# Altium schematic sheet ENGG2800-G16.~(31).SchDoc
size A3
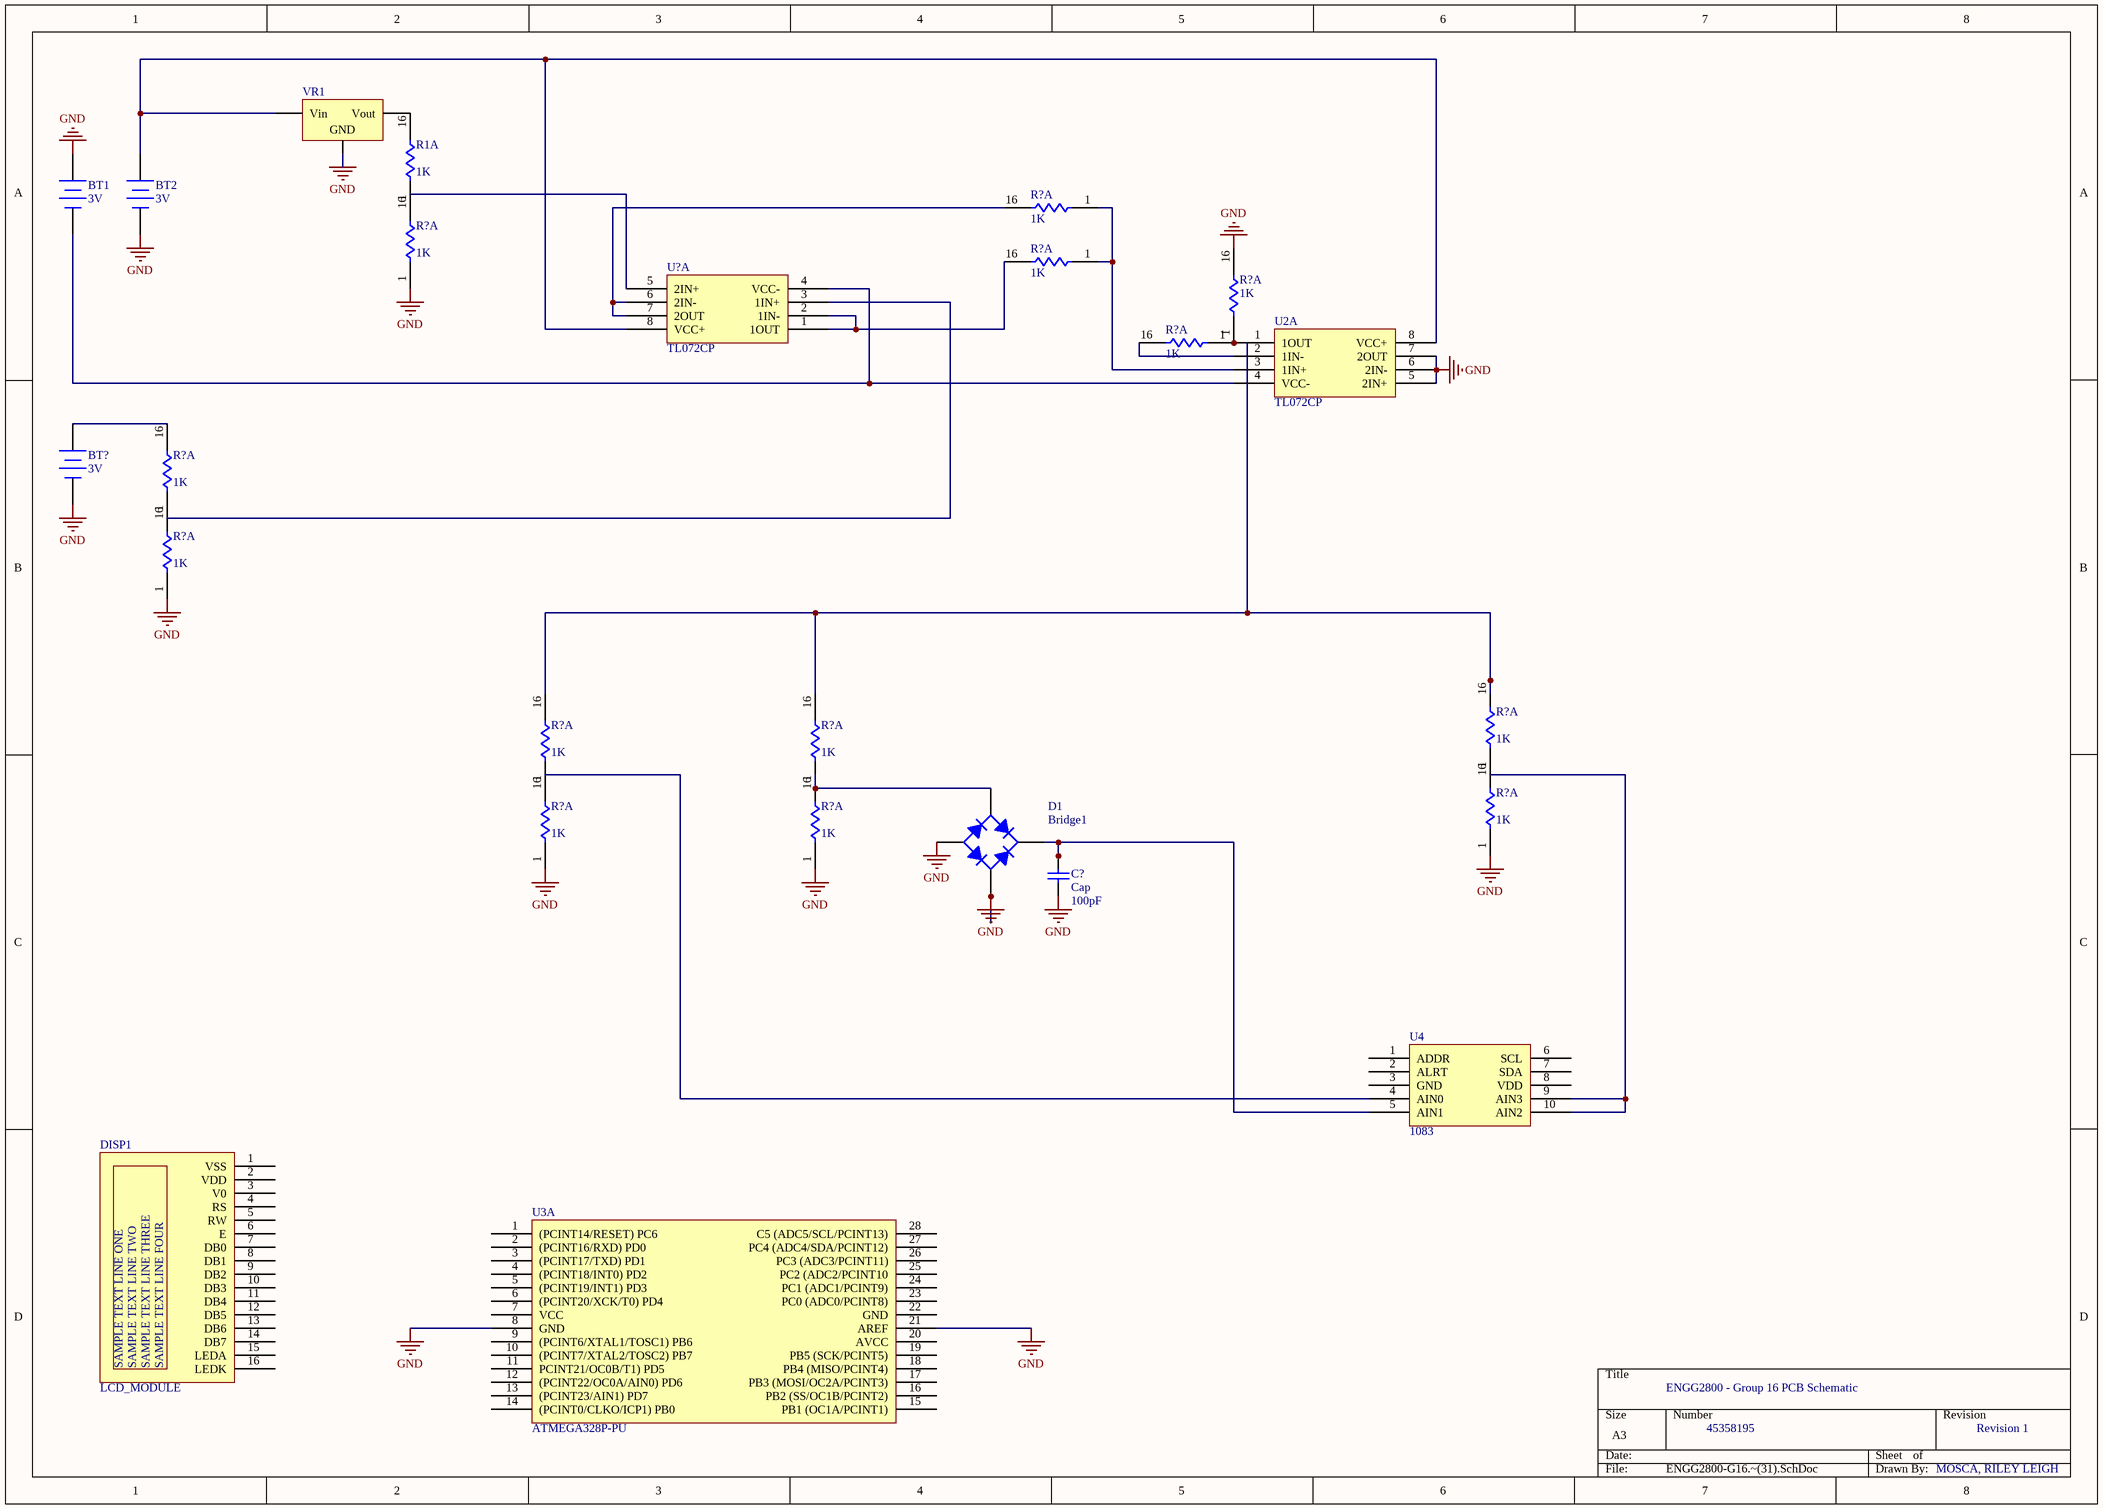
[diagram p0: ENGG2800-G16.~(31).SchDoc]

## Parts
(Parts that share a designator on the sheet are numbered #1, #2 ... from top to bottom, then left to right.)
BT1  3V  [BAT-2]
BT2  3V  [BAT-2]
BT?  3V  [BAT-2]
C?  Cap  value 100pF  [RAD-0.3]
D1  Bridge1  [D-38]
DISP1  LCD_MODULE
R1  value 1K  [SOIC16_N]  (hidden comment: Res Pack1)  (part A of 8)
R?#1  value 1K  [SOIC16_N]  (hidden comment: Res Pack1)  (part A of 8)
R?#2  value 1K  [SOIC16_N]  (hidden comment: Res Pack1)  (part A of 8)
R?#3  value 1K  [SOIC16_N]  (hidden comment: Res Pack1)  (part A of 8)
R?#4  value 1K  [SOIC16_N]  (hidden comment: Res Pack1)  (part A of 8)
R?#5  value 1K  [SOIC16_N]  (hidden comment: Res Pack1)  (part A of 8)
R?#6  value 1K  [SOIC16_N]  (hidden comment: Res Pack1)  (part A of 8)
R?#7  value 1K  [SOIC16_N]  (hidden comment: Res Pack1)  (part A of 8)
R?#8  value 1K  [SOIC16_N]  (hidden comment: Res Pack1)  (part A of 8)
R?#9  value 1K  [SOIC16_N]  (hidden comment: Res Pack1)  (part A of 8)
R?#10  value 1K  [SOIC16_N]  (hidden comment: Res Pack1)  (part A of 8)
R?#11  value 1K  [SOIC16_N]  (hidden comment: Res Pack1)  (part A of 8)
R?#12  value 1K  [SOIC16_N]  (hidden comment: Res Pack1)  (part A of 8)
R?#13  value 1K  [SOIC16_N]  (hidden comment: Res Pack1)  (part A of 8)
U2  TL072CP  (part A of 4)
U3  ATMEGA328P-PU  (part A of 2)
U4  1083
U?  TL072CP  (part A of 4)
VR1  Volt Reg  [D2PAK_N]  (value not drawn)

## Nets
GND: BT1.1(+) BT2.2(-) BT?.2(-) C?.1 D1.2(C) D1.3(A) R?#2.1 R?#4.16 R?#7.1 R?#11.1 R?#12.1 R?#13.1 U2.5(2IN+) U2.6(2IN-) U2.7(2OUT) U3.8(GND) U3.21(AREF) VR1.2(GND)
NetBT1_2: BT1.2(-) U2.4(VCC-) U?.4(VCC-)
NetBT2_1: BT2.1(+) U2.8(VCC+) U?.8(VCC+) VR1.1(Vin)
NetBT?_1: BT?.1(+) R?#6.16
NetC?_2: C?.2 D1.1(K) U4.5(AIN1)
NetD1_4: D1.4(C) R?#10.1 R?#13.16
NetR1_16: R1.16 VR1.3(Vout)
NetR?#1_1: R?#1.1 R?#3.1 U2.3(1IN+)
NetR?#1_16: R?#1.16 U?.6(2IN-) U?.7(2OUT)
NetR?#2_16: R?#2.16 U?.5(2IN+)
NetR?#3_16: R?#3.16 U?.1(1OUT) U?.2(1IN-)
NetR?#4_1: R?#4.1 R?#5.1 U2.1(1OUT)
NetR?#5_16: R?#5.16 U2.2(1IN-)
NetR?#6_1: R?#6.1 U?.3(1IN+)
NetR?#8_1: R?#8.1 U4.9(AIN3) U4.10(AIN2)
NetR?#8_16: R?#8.16 R?#9.16 R?#10.16
NetR?#12_16: R?#12.16 U4.4(AIN0)

Not connected (* = marked no-connect by the designer): DISP1 1(VSS) 2(VDD) 3(V0) 4(RS) 5(RW) 6(E) 7(DB0) 8(DB1) 9(DB2) 10(DB3) 11(DB4) 12(DB5) 13(DB6) 14(DB7) 15(LEDA) 16(LEDK); R1 1; R?#7 16; R?#9 1; R?#11 16; U3 1((PCINT14/RESET)_PC6) 2((PCINT16/RXD)_PD0) 3((PCINT17/TXD)_PD1) 4((PCINT18/INT0)_PD2) 5((PCINT19/INT1)_PD3) 6((PCINT20/XCK/T0)_PD4) 7(VCC) 9((PCINT6/XTAL1/TOSC1)_PB6) 10((PCINT7/XTAL2/TOSC2)_PB7) 11(PCINT21/OC0B/T1)_PD5) 12((PCINT22/OC0A/AIN0)_PD6) 13((PCINT23/AIN1)_PD7) 14((PCINT0/CLKO/ICP1)_PB0) 15(PB1_(OC1A/PCINT1)) 16(PB2_(SS/OC1B/PCINT2)) 17(PB3_(MOSI/OC2A/PCINT3)) 18(PB4_(MISO/PCINT4)) 19(PB5_(SCK/PCINT5)) 20(AVCC) 22(GND) 23(PC0_(ADC0/PCINT8)) 24(PC1_(ADC1/PCINT9)) 25(PC2_(ADC2/PCINT10) 26(PC3_(ADC3/PCINT11)) 27(PC4_(ADC4/SDA/PCINT12)) 28(C5_(ADC5/SCL/PCINT13)); U4 1(ADDR) 2(ALRT) 3(GND) 6(SCL) 7(SDA) 8(VDD)

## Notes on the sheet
- ENGG2800 - Group 16 PCB Schematic
- 45358195
- Revision 1
- MOSCA, RILEY LEIGH

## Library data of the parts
BT1 BT2 BT? = Battery: Multicell Battery
C? = Cap: Capacitor
D1 = Bridge1: Full Wave Diode Bridge
R1 R?#1-R?#13 = Res Pack1: Isolated Resistor Network - Parts; Sim Note: Enter the Resistance value into parameter field.
U2 U? = TL072CP: IC, OP AMP, DUAL JFET, DIP8; Bandwidth:3MHz; No. of Amplifiers:2; Slew Rate:13V/ s; Supply Voltage Range:7V to 36V; Amplifier Case Style:DIP; No. of Pins:8; Operating Temperature Min:0 C; Operating Temperature Max:70 C; ;RoHS Compliant: Yes; Manufacturer: Texas Instruments; Bandwidth: 3MHz; Number of Channels: 2; Voltage Gain: 106.02dB; Nominal Supply Current: 5mA; Max Supply Voltage: 18V; Min Dual Supply Voltage: 3.5V; Dual Supply Voltage: 9V; Common Mode Rejection Ratio: 70dB; Slew Rate: 13V/µs; Max I/O Voltage: 10mV; Input Bias Current: 200pA; Input Offset Voltage (Vos): 3mV; Operating Supply Current: 1.4mA
U3 = ATMEGA328P-PU: IC MCU 8BIT 32KB FLASH 28DIP; Manufacturer: Microchip / Atmel; Core Architecture: AVR; RAM Size: 2KB; Number of PWM Channels: 6; Number of Timers/Counters: 3; Min Supply Voltage: 1.8V; Max Supply Voltage: 5.5V; Interface: I2C,SPI,UART,USART,2-Wire; Number of I/Os: 23; Frequency: 20MHz; Oscillator Type: Internal; Data Bus Width: 8b; Number of SPI Channels: 1; Watchdog Timer: Yes; Peripherals: Brown-out Detect/Reset,POR,PWM,WDT
U4 = 1083: EVAL BOARD ADS1115 16-BIT ADC; Manufacturer: Adafruit Industries; Number of Bits: 12; Evaluation Kit: Yes; Number of A/D Converters: 1; Sampling Rate: 3300S/s; Interface: I2C,Serial
VR1 = Volt Reg: Voltage Regulator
